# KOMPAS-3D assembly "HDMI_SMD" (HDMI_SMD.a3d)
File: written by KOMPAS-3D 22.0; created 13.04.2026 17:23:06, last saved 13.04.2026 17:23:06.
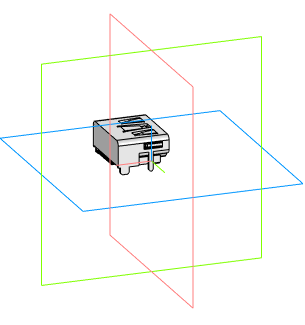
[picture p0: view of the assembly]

Document properties: Автор: Andrey; Полное имя файла: C:\Users\User1\Documents\HDMI_SMD.a3d

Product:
- Component [detail]: 1747981-2-g  | qty 1  | source file: 1747981-2-g.m3d
- Part/product: HDMI_SMD
    Комментарий: HDMI_SMD

Referenced files in C:\Users\User1\Documents\: 1747981-2-g.m3d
